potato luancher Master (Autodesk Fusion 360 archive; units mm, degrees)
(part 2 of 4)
sketch "handle moch" plane through (0, 0, 0) normal (1, 0, 0) x axis (0, 1, 0)
  line L1 (69.594, 159.512) -> (83.818, 159.512)
  line L2 (69.594, 145.288) -> (69.594, 159.512)
  line L3 (83.818, 145.288) -> (69.594, 145.288)
  line L4 (83.818, 159.512) -> (83.818, 145.288)
  line L5 (120.5924, 62.217) -> (106.3261, 115.4598)
  line L6 (81.1484, 62.217) -> (120.5924, 62.217)
  line L7 (67.4557, 113.3189) -> (81.1484, 62.217)
  line L8 (457.7082, 152.4) -> (76.706, 152.4)
  line L9 (432.306, 167.4813) -> (305.306, 167.4812)
  line L10 (432.306, 137.3187) -> (432.306, 167.4813)
  line L11 (305.306, 137.3187) -> (432.306, 137.3187)
  line L12 (305.306, 167.4812) -> (305.306, 137.3187)
  line L13 (432.306, 137.3187) -> (305.306, 167.4812)
  line L14 (305.306, 137.3187) -> (432.306, 167.4813)
  line L15 (476.756, 88.9) -> (476.756, -88.9)
  line L16 (44.956, 88.9) -> (44.956, -88.9)
  line L17 (476.756, 88.9) -> (44.956, 88.9)
  line L18 (458.1373, 88.9) -> (432.306, 167.4813)
  line L19 (420.2222, 88.9) -> (404.3059, 137.3187)
  arc A1 centre (76.706, 152.4) radius 25.4 clockwise from (55.9925, 137.6992) to (102.0952, 151.6607)
  arc A2 centre (227.7719, 148.0011) radius 125.73 clockwise from (106.3261, 115.4598) to (102.0952, 151.6607)
  arc A3 centre (-6.1479, 93.5969) radius 76.2 clockwise from (55.9925, 137.6992) to (67.4557, 113.3189)
  circle C1 centre (76.706, 152.4) radius 15.0813
  circle C2 centre (76.706, 152.4) radius 15.0813
  point P15 (76.706, 152.4)
  point P16 (76.706, 152.4)
  point P22 (368.806, 152.4)
  point P26 (44.956, 88.9)
  point P27 (44.956, 88.9)
  point P24 (476.756, 88.9)
  point P28 (476.756, 88.9)
  point P29 (458.1373, 88.9)
  point P30 (404.3059, 137.3187)
  point P31 (420.2222, 88.9)
  point P18 (305.306, 167.4812)
  point P21 (305.306, 137.3187)
  point P19 (432.306, 167.4813)
  coincident P15 P16
  perpendicular L4 L8
  horizontal L9
  perpendicular L9 L10
  parallel L9 L11
  parallel L10 L12
  coincident L13 P22
  coincident L14 P22
  coincident L8 P22
  coincident P26 P27
  coincident P24 P28
  coincident L17 P29
  coincident L11 P30
  coincident L17 P31
  parallel L18 L19
  dimension "d214" distance P18 P21 = 30.1625 (= "d215")
  dimension "d215" diameter C2 = 30.1625
  dimension "d216" distance P18 P19 = 127
  dimension "d217" distance P15 L12 = 228.6
extrude "Extrude1" new body sketch "handle moch" profile of L9 L10 L11 L12 L17 L18 L19 distance 31.75
sketch "Sketch1" plane through (0, 0, 0) normal (0, 1, 0) x axis (-1, 0, 0)
  line L1 (7.9375, -2.4765) -> (-7.9375, -2.4765)
  line L2 (7.9375, 2.4765) -> (7.9375, -2.4765)
  line L3 (-7.9375, 2.4765) -> (7.9375, 2.4765)
  line L4 (-7.9375, -2.4765) -> (-7.9375, 2.4765)
  line L5 (7.9375, 2.4765) -> (-7.9375, -2.4765)
  line L6 (-7.9375, 2.4765) -> (7.9375, -2.4765)
  line L7 (-8.0375, 2.4765) -> (-7.9375, 2.4765)
  line L8 (-8.0375, -2.4765) -> (-8.0375, 2.4765)
  line L9 (-7.9375, -2.4765) -> (-8.0375, -2.4765)
  line L10 (-7.9375, 2.4765) -> (-7.9375, -2.4765)
  line L11 (-9.7875, 2.4765) -> (-8.0375, 2.4765)
  line L12 (-9.7875, -2.5765) -> (-9.7875, 2.4765)
  line L13 (-8.0375, -2.5765) -> (-9.7875, -2.5765)
  line L14 (-8.0375, 2.4765) -> (-8.0375, -2.5765)
  line L15 (-22.5, 0) -> (-1.75, 0)
  line L16 (-9.7855, 2.4765) -> (-7.9375, 2.4765)
  line L17 (-9.7855, 4.81) -> (-9.7855, 2.4765)
  line L18 (-7.9375, 4.81) -> (-9.7855, 4.81)
  line L19 (-7.9375, 2.4765) -> (-7.9375, 4.81)
  line L20 (-15.4644, 4.81) -> (-9.7855, 4.81)
  line L21 (-15.4644, 3.7178) -> (-15.4644, 4.81)
  line L22 (-11.0939, 1.9413) -> (-15.4644, 3.7178)
  line L23 (-15.4644, -4.81) -> (-9.7855, -4.81)
  line L24 (-7.9375, -4.81) -> (-9.7855, -4.81)
  line L25 (-7.9375, -2.4765) -> (-7.9375, -4.81)
  line L26 (-11.0939, -1.9413) -> (-15.4644, -3.7178)
  line L27 (-15.4644, -3.7178) -> (-15.4644, -4.81)
  line L28 (-8.0375, -4.81) -> (-8.0375, -2.5765)
  line L29 (-8.0375, 4.81) -> (-8.0375, 2.4765)
  line L30 (-8.0375, -4.81) -> (-6.7375, -4.81)
  line L31 (-8.0375, -2.5765) -> (-8.0375, -4.81)
  line L32 (-6.7375, -2.5765) -> (-8.0375, -2.5765)
  line L33 (-6.7375, -4.81) -> (-6.7375, -2.5765)
  circle C1 centre (-11.883, 0) radius 2.0955
  point P6 (0, 0)
  point P1 (0, 0)
  point P13 (-11.883, 0)
  point P5 (-7.9375, 2.4765)
  point P24 (-7.9375, -2.4765)
  point P17 (-9.7855, 4.81)
  point P21 (-9.7855, -4.81)
  point P18 (-7.9375, 4.81)
  point P23 (-7.9375, -4.81)
  point P19 (-15.4644, 4.81)
  point P22 (-15.4644, -4.81)
  point P20 (-15.4644, 3.7178)
  point P25 (-15.4644, -3.7178)
  point P26 (-8.0375, -4.81)
  point P27 (-8.0375, 4.81)
  point P28 (-11.0939, 1.9413)
  point P29 (-11.0939, -1.9413)
  point P4 (7.9375, 2.4765)
  point P3 (7.9375, -2.4765)
  point P7 (-8.0375, 2.4765)
  point P10 (-9.7875, 2.4765)
  horizontal L1
  perpendicular L1 L2
  parallel L1 L3
  parallel L2 L4
  coincident L5 P6
  coincident L6 P6
  coincident P1 P6
  horizontal L7
  vertical L8
  horizontal L9
  vertical L10
  horizontal L11
  vertical L12
  horizontal L13
  vertical L14
  coincident P13 L15
  horizontal L16
  vertical L17
  horizontal L18
  vertical L19
  tangent L12 C1
  perpendicular L17 L20
  perpendicular L20 L21
  tangent C1 L22
  symmetric P5 L15 P24
  symmetric L15 P17 P21
  symmetric L15 P18 P23
  symmetric L15 P19 P22
  symmetric L15 P20 P25
  coincident L24 P26
  perpendicular L24 L28
  coincident L18 P27
  perpendicular L18 L29
  coincident C1 P28
  coincident C1 P29
  tangent C1 L26
  horizontal L30
  vertical L31
  horizontal L32
  vertical L33
  coincident P23 L30
  dimension "d220" distance P4 P5 = 15.875
  dimension "d221" distance P3 P4 = 4.953
  dimension "d222" distance P5 P7 = 0.1
  dimension "d223" distance P7 P10 = 1.75
  dimension "d224" diameter C1 = 4.191
  dimension "d225" distance P19 P20 = 1.0922
  dimension "d229" distance L20 L23 = 9.62 (= "0.3 in + 2 mm")
  dimension "d230" distance P13 L27 = 3.5814
  dimension "d231" distance L1 L32 = 0.1 (= "d222")
  dimension "d232" distance L10 L33 = 1.2
revolve "Revolve1" sketch "Sketch1" AlongAngle 360
sketch "spring anchor align" plane through (0, 476.756, 0) normal (0, 1, 0) x axis (-1, 0, 0)
  line L1 (-49.3991, 88.7823) -> (-43.2242, 77.6845)
  line L2 (-52.1735, 87.2385) -> (-49.3991, 88.7823)
  line L3 (-45.9987, 76.1408) -> (-52.1735, 87.2385)
  line L4 (-43.2242, 77.6845) -> (-45.9987, 76.1408)
  line L5 (-52.7144, 94.7406) -> (-49.3991, 88.7823)
  line L6 (-55.4888, 93.1969) -> (-52.7144, 94.7406)
  line L7 (-52.1735, 87.2385) -> (-55.4888, 93.1969)
  line L8 (-49.3991, 88.7823) -> (-52.1735, 87.2385)
  line L9 (0, -29.1936) -> (0, 113.1666)
  line L10 (-2, 90.4654) -> (-2, 108.4001)
  line L11 (0, 0) -> (-50.9577, 95.6969)
  circle C1 centre (0, 0) radius 108.4186
  circle C2 centre (0, 0) radius 88.9
  circle C3 centre (0, 0) radius 88.9
  circle C4 centre (0, 0) radius 90.4875
  point P1 (0, 0)
  point P12 (0, 0)
  point P7 (-52.7144, 94.7406)
  point P14 (-2, 108.4001)
  point P16 (-50.9577, 95.6969)
  point P17 (0, 0)
  point P15 (-2, 90.4654)
  coincident P1 L9
  vertical L9
  coincident P1 P12
  coincident P7 C1
  coincident C1 P14
  parallel L9 L10
  coincident C1 P16
  coincident P1 P17
  coincident P15 C4
  dimension "d233" distance P7 L11 = 2
  dimension "d234" distance L9 L10 = 2 (= "d233")
extrude "Extrude1" new body sketch "spring anchor align" profile of L1 L5 L9 C1 C2 C3 L10 L11 C4 against normal blind 25.4
work_plane "WorkPlane22"
sketch "sp anchor align lable" plane through (26.4789, 0, 102.0485) normal (-0.2512, 0, -0.9679) x axis (0, -1, 0)
  dimension "d540" = 10.0076
emboss "Emboss1" sketch "sp anchor align lable" Depth 2.0066 Horizontal Distance 0 Vertical Distance 0 Rotation Angle 0
extrude "Extrude2" add sketch "spring anchor align" profile of L1 L5 L9 C1 C2 C3 L10 L11 C4 blind -2 from offset -25.4
remove_body "RemoveBody1"
sketch "Sketch2" plane through (0, 76.706, 0) normal (0, -1, 0) x axis (-1, 0, 0)
  line L1 (-66.675, -158.75) -> (66.675, -158.75)
  line L2 (-66.675, -146.05) -> (-66.675, -158.75)
  line L3 (66.675, -146.05) -> (-66.675, -146.05)
  line L4 (66.675, -158.75) -> (66.675, -146.05)
  line L5 (0, -194.1437) -> (0, -158.75)
  line L6 (66.675, -151.6607) -> (63.5, -151.6607)
  line L7 (66.675, -177.8) -> (66.675, -137.6992)
  line L8 (63.5, -137.6992) -> (66.675, -137.6992)
  line L9 (63.5, -177.8) -> (63.5, -137.6992)
  line L10 (61.43, -177.8) -> (63.43, -177.8)
  line L11 (60.43, -167.4813) -> (61.43, -177.8)
  line L12 (0, -167.4813) -> (60.43, -167.4813)
  line L13 (-63.5, -167.4812) -> (-63.5, -137.3187)
  line L14 (-60.43, -167.4813) -> (-61.43, -177.8)
  line L15 (-61.43, -177.8) -> (-63.5, -177.8)
  line L16 (0, -167.4813) -> (-60.43, -167.4813)
  line L17 (-63.5, -158.05) -> (-63.5, -177.8)
  line L18 (63.43, -177.8) -> (63.5, -177.8)
  line L19 (63.43, -158.75) -> (63.43, -177.8)
  line L20 (63.5, -158.75) -> (63.43, -158.75)
  line L21 (63.5, -177.8) -> (63.5, -158.75)
  line L22 (-63.43, -177.8) -> (-63.5, -177.8)
  line L23 (-63.43, -158.75) -> (-63.43, -177.8)
  line L24 (-63.5, -158.75) -> (-63.43, -158.75)
  line L25 (-63.5, -177.8) -> (-63.5, -158.75)
  line L26 (-63.5, -177.8) -> (-63.5, -127)
  line L27 (63.5, -146.05) -> (63.43, -158.75)
  line L28 (42.3915, -152.4) -> (63.465, -152.4)
  point P6 (0, -158.75)
  point P16 (0, -167.4813)
  point P18 (-63.5, -167.4812)
  point P14 (61.43, -177.8)
  point P19 (-61.43, -177.8)
  point P15 (60.43, -167.4813)
  point P20 (-60.43, -167.4813)
  point P22 (0, -167.4813)
  point P23 (-63.5, -158.05)
  point P27 (63.43, -158.75)
  point P13 (63.5, -177.8)
  point P25 (63.5, -177.8)
  point P24 (63.43, -177.8)
  point P26 (63.43, -177.8)
  point P30 (-63.43, -158.75)
  point P34 (63.5, -146.05)
  point P35 (63.465, -152.4)
  point P36 (63.465, -152.4)
  midpoint L1 P6
  perpendicular L1 L5
  perpendicular L9 L10
  coincident L5 P16
  perpendicular L5 L12
  coincident L12 P18
  symmetric L5 P14 P19
  symmetric L5 P15 P20
  symmetric L5 P16 P22
  coincident L13 P23
  perpendicular L1 L17
  horizontal L18
  vertical L19
  horizontal L20
  vertical L21
  coincident L1 P27
  coincident P13 P25
  coincident P24 P26
  horizontal L15
  horizontal L22
  vertical L23
  horizontal L24
  vertical L25
  coincident L1 P30
  coincident L9 P34
  coincident L3 P34
  midpoint L27 P35
  coincident P35 P36
  perpendicular L9 L28
  dimension "d240" distance P25 P26 = 0.07
  dimension "d241" distance P14 P24 = 2
  dimension "d242" distance P15 P24 = 3 (= "d241 * 1.5")
  dimension "d243" distance L23 L26 = 0.07
revolve "Revolve1" sketch "Sketch2" AlongAngle 360
sketch "Sketch22" plane through (-63.43, 0, 0) normal (-1, 0, 0) x axis (0, -1, 0)
  line L1 (-83.056, 158.75) -> (-70.356, 158.75)
  line L2 (-83.056, 146.05) -> (-83.056, 158.75)
  line L3 (-70.356, 146.05) -> (-83.056, 146.05)
  line L4 (-70.356, 158.75) -> (-70.356, 146.05)
  line L5 (-70.156, 145.85) -> (-83.256, 145.85)
  line L6 (-70.156, 158.95) -> (-70.156, 145.85)
  line L7 (-83.256, 158.95) -> (-70.156, 158.95)
  line L8 (-83.256, 145.85) -> (-83.256, 158.95)
  circle C1 centre (-76.706, 152.4) radius 6.35
  circle C2 centre (-76.706, 152.4) radius 25.4
  point P3 (-70.356, 158.75)
  point P6 (-70.356, 146.05)
  dimension "d300" distance P3 P6 = 12.7
  dimension "d301" = 0.2
extrude "Extrude1" cut sketch "Sketch22" profile of C1 L1 L2 L3 L4 L8 L7 L6 L5 against normal blind 126.93
work_plane "WorkPlane1" AlongDistance 17.78
sketch "Sketch3" plane through (0, 52.576, 0) normal (0, -1, 0) x axis (-1, 0, 0)
  line L1 (60.43, -167.4813) -> (60.43, -137.3187)
  line L2 (-60.43, -167.4813) -> (-60.43, -137.3187)
  line L3 (60.43, -167.4813) -> (-60.43, -167.4813)
  line L4 (-60.43, -137.3187) -> (60.43, -137.3187)
  line L5 (-60.43, -152.4) -> (60.43, -152.4)
  line L6 (-27.6126, -276.5613) -> (-13.2272, -282.3759)
  line L7 (-41.998, -282.3759) -> (-27.6126, -276.5613)
  line L8 (-56.3834, -276.5613) -> (-41.998, -282.3759)
  line L9 (-70.7688, -282.3759) -> (-56.3834, -276.5613)
  line L10 (-85.1541, -276.5613) -> (-70.7688, -282.3759)
  line L11 (-99.5395, -282.3759) -> (-85.1541, -276.5613)
  line L12 (-113.9249, -276.5613) -> (-99.5395, -282.3759)
  line L13 (-128.3103, -282.3759) -> (-113.9249, -276.5613)
  line L14 (-142.6957, -276.5613) -> (-128.3103, -282.3759)
  line L15 (-157.0811, -282.3759) -> (-142.6957, -276.5613)
  line L16 (1.1582, -276.5613) -> (-13.2272, -282.3759)
  line L17 (-157.0811, -276.5613) -> (1.1582, -276.5613)
  line L18 (-157.0811, -282.3759) -> (-157.0811, -276.5613)
  line L19 (1.1582, -282.3759) -> (-157.0811, -282.3759)
  line L20 (1.1582, -276.5613) -> (1.1582, -282.3759)
  line L21 (1.9077, -278.4156) -> (-13.2272, -284.533)
  line L22 (-27.6126, -278.7185) -> (-13.2272, -284.533)
  line L23 (-41.998, -284.533) -> (-27.6126, -278.7185)
  line L24 (-56.3834, -278.7185) -> (-41.998, -284.533)
  line L25 (-70.7688, -284.533) -> (-56.3834, -278.7185)
  line L26 (-85.1541, -278.7185) -> (-70.7688, -284.533)
  line L27 (-99.5395, -284.533) -> (-85.1541, -278.7185)
  line L28 (-113.9249, -278.7185) -> (-99.5395, -284.533)
  line L29 (-128.3103, -284.533) -> (-113.9249, -278.7185)
  line L30 (-142.6957, -278.7185) -> (-128.3103, -284.533)
  line L31 (-156.3316, -284.2301) -> (-142.6957, -278.7185)
  curve K1 (56.6004, -155.7426) -> (50.2504, -151.5646)
  curve K2 (43.9004, -147.3866) -> (50.2504, -151.5646)
  line L32 (37.5504, -151.5646) -> (62.9504, -151.5646)
  line L33 (56.6004, -147.3866) -> (56.6004, -155.7426)
  line L34 (43.9004, -155.7426) -> (43.9004, -147.3866)
  line L35 (37.5504, -151.5646) -> (50.2504, -151.5646)
  line L36 (62.9504, -151.5646) -> (50.2504, -151.5646)
  curve K3 (31.2004, -155.7426) -> (24.8504, -151.5646)
  curve K4 (18.5004, -147.3866) -> (24.8504, -151.5646)
  curve K5 (5.8004, -155.7426) -> (-0.5496, -151.5646)
  curve K6 (-6.8996, -147.3866) -> (-0.5496, -151.5646)
  curve K7 (-19.5996, -155.7426) -> (-25.9496, -151.5646)
  curve K8 (-32.2996, -147.3866) -> (-25.9496, -151.5646)
  curve K9 (-44.9996, -155.7426) -> (-51.3496, -151.5646)
  curve K10 (-57.6996, -147.3866) -> (-51.3496, -151.5646)
  curve K11 (49.1511, -153.2354) -> (64.0496, -153.2354)
  curve K12 (49.1511, -153.2354) -> (38.6496, -153.2354)
  curve K13 (23.7511, -153.2354) -> (38.6496, -153.2354)
  curve K14 (23.7511, -153.2354) -> (13.2496, -153.2354)
  curve K15 (-1.6489, -153.2354) -> (13.2496, -153.2354)
  curve K16 (-1.6489, -153.2354) -> (-12.1504, -153.2354)
  curve K17 (-27.0489, -153.2354) -> (-12.1504, -153.2354)
  curve K18 (-27.0489, -153.2354) -> (-37.5504, -153.2354)
  curve K19 (-52.4489, -153.2354) -> (-37.5504, -153.2354)
  curve K20 (-52.4489, -153.2354) -> (-62.9504, -153.2354)
  line L37 (-62.9504, -131.0687) -> (-62.9504, -153.2354)
  line L38 (62.9504, -173.7313) -> (62.9504, -151.5646)
  line L39 (-62.9504, -131.0687) -> (62.9504, -173.7313)
  point P5 (-60.43, -167.4813)
  point P6 (-60.43, -167.4813)
  point P3 (60.43, -167.4813)
  point P7 (60.43, -167.4813)
  point P2 (60.43, -137.3187)
  point P8 (60.43, -137.3187)
  point P4 (-60.43, -137.3187)
  point P9 (-60.43, -137.3187)
  point P10 (60.43, -152.4)
  point P11 (-60.43, -152.4)
  point P12 (-13.2272, -282.3759)
  point P14 (-41.998, -282.3759)
  point P18 (-99.5395, -282.3759)
  point P20 (-128.3103, -282.3759)
  point P21 (-142.6957, -276.5613)
  point P15 (-56.3834, -276.5613)
  point P39 (50.2504, -151.5646)
  point P41 (50.2504, -151.5646)
  point P43 (37.5504, -151.5646)
  point P45 (37.5504, -151.5646)
  point P38 (62.9504, -151.5646)
  point P44 (62.9504, -151.5646)
  point P85 (0, -152.4)
  point P86 (0, -152.4)
  coincident P5 P6
  coincident P3 P7
  coincident P2 P8
  coincident P4 P9
  midpoint L1 P10
  midpoint L2 P11
  parallel L6 L8
  parallel L7 L9
  parallel L11 L13
  parallel L13 L15
  equal L14 L15
  equal L13 L14
  equal L11 L12
  equal L12 L13
  equal L10 L11
  equal L8 L9
  equal L9 L10
  equal L7 L8
  equal L6 L7
  equal L6 L16
  horizontal L17
  vertical L18
  horizontal L19
  vertical L20
  coincident P12 L19
  coincident P14 L19
  coincident P18 L19
  coincident P20 L19
  coincident P21 L17
  coincident P15 L17
  coincident P39 P41
  horizontal L32
  coincident P43 P45
  coincident P38 P44
  coincident P39 L32
  vertical L33
  vertical L34
  midpoint L34 L35
  midpoint L33 L36
  equal L33 L34
  equal L35 L36
  vertical L37
  perpendicular L36 L38
  equal L37 L38
  coincident L39 P85
  midpoint L39 P85
  midpoint L5 P86
  coincident P85 P86
  dimension "d245" = -2
  dimension "d247" distance P38 P43 = 25.4
  dimension "d252" = -2
  dimension "d250" R-Pattern1-uDistance = -25.4
  dimension "d251" R-Pattern1-vDistance = 0
emboss "Emboss1" sketch "Sketch3" Depth 1.3 Horizontal Distance 0 Vertical Distance 0 Rotation Angle 0
circular_pattern "C-Pattern1" countU 17 TotalAngle 360
sketch "Sketch2" plane through (0, 0, 0) normal (0, 1, 0) x axis (1, 0, 0)
  line L1 (6.7375, 2.5765) -> (-6.7375, 2.5765)
  line L2 (6.7375, 4.81) -> (-6.7375, 4.81)
  line L3 (15.4644, -4.81) -> (-15.4644, -4.81)
  line L4 (0, -45.2489) -> (0, 7.043)
  line L5 (-3.175, 2.5765) -> (3.175, 2.5765)
  line L6 (-3.175, -16.4735) -> (-3.175, 2.5765)
  line L7 (3.175, -16.4735) -> (-3.175, -16.4735)
  line L8 (3.175, 2.5765) -> (3.175, -16.4735)
  line L9 (-3.175, -16.4735) -> (3.175, 2.5765)
  line L10 (3.175, -16.4735) -> (-3.175, 2.5765)
  line L11 (-4.7117, 8.9265) -> (4.7117, 8.9265)
  line L12 (-4.7117, 2.5765) -> (-4.7117, 8.9265)
  line L13 (4.7117, 2.5765) -> (-4.7117, 2.5765)
  line L14 (4.7117, 8.9265) -> (4.7117, 2.5765)
  line L15 (-4.7117, 2.5765) -> (4.7117, 8.9265)
  line L16 (4.7117, 2.5765) -> (-4.7117, 8.9265)
  line L17 (3.175, -16.4735) -> (-3.175, -16.4735)
  line L18 (3.175, -9.6663) -> (3.175, -16.4735)
  line L19 (-3.175, -9.6663) -> (3.175, -9.6663)
  line L20 (-3.175, -16.4735) -> (-3.175, -9.6663)
  line L21 (13.3232, -9.6663) -> (-4.8965, -9.6663)
  line L22 (13.3232, -6.4913) -> (13.3232, -9.6663)
  line L23 (-4.8965, -6.4913) -> (13.3232, -6.4913)
  line L24 (-4.8965, -9.6663) -> (-4.8965, -6.4913)
  line L25 (15.4644, 4.81) -> (15.4644, -4.81)
  line L26 (21.2101, 0) -> (15.4644, 0)
  line L27 (6.7375, -2.5765) -> (-6.7375, -2.5765)
  line L28 (3.325, -6.4913) -> (3.325, -2.5765)
  line L29 (4.849, -2.5765) -> (4.849, -6.4913)
  point P14 (0, -6.9485)
  point P1 (0, 0)
  point P19 (0, 5.7515)
  point P10 (3.175, 2.5765)
  point P21 (3.175, -9.6663)
  point P18 (4.7117, 2.5765)
  point P7 (15.4644, -4.81)
  point P27 (15.4644, -4.81)
  point P28 (15.4644, 4.81)
  point P29 (15.4644, 0)
  point P2 (-6.7375, 2.5765)
  point P31 (-6.7375, -2.5765)
  point P3 (6.7375, 2.5765)
  point P32 (6.7375, -2.5765)
  point P33 (3.325, -2.5765)
  point P34 (3.325, -6.4913)
  point P35 (4.849, -6.4913)
  point P36 (4.849, -2.5765)
  point P11 (-3.175, 2.5765)
  point P12 (-3.175, -16.4735)
  point P13 (3.175, -16.4735)
  point P17 (-4.7117, 2.5765)
  point P16 (-4.7117, 8.9265)
  point P24 (13.3232, -9.6663)
  point P25 (13.3232, -6.4913)
  perpendicular L3 L4
  horizontal L5
  perpendicular L5 L6
  parallel L5 L7
  parallel L6 L8
  coincident L9 P14
  coincident L10 P14
  coincident L4 P14
  coincident P1 L4
  horizontal L11
  perpendicular L11 L12
  parallel L11 L13
  parallel L12 L14
  coincident L15 P19
  coincident L16 P19
  coincident L4 P19
  coincident P10 L13
  horizontal L17
  vertical L18
  horizontal L19
  vertical L20
  coincident L8 P21
  coincident L1 P18
  horizontal L21
  vertical L22
  horizontal L23
  vertical L24
  coincident P21 L21
  coincident P7 P27
  vertical L25
  coincident L2 P28
  midpoint L25 P29
  perpendicular L25 L26
  symmetric P2 L26 P31
  symmetric P3 L26 P32
  coincident L27 P33
  coincident L23 P34
  perpendicular L23 L28
  coincident L23 P35
  coincident L27 P36
  perpendicular L27 L29
  dimension "d273" distance P11 P12 = 19.05
  dimension "d274" distance P12 P13 = 6.35
  dimension "d275" distance P17 P18 = 9.4234
  dimension "d276" distance P16 P17 = 6.35
  dimension "d277" distance L7 L19 = 6.8072 (= "0.308 in - 0.04 in")
  dimension "d278" distance P24 P25 = 3.175
  dimension "d279" distance L8 L28 = 0.15
  dimension "d280" distance L28 L29 = 1.524
work_plane "WorkPlane23" AlongDistance 127
sketch "Fwd ahndle align" plane through (0, 127, 0) normal (0, 1, 0) x axis (1, 0, 0)
  line L1 (0, -131.9689) -> (0, 0)
  line L2 (-3, -131.9689) -> (-3, 0)
  line L3 (-63.5, -115.4598) -> (-66.675, -115.4598)
  line L4 (-63.5, -62.217) -> (-63.5, -115.4598)
  line L5 (-66.675, -62.217) -> (-63.5, -62.217)
  line L6 (-66.675, -115.4598) -> (-66.675, -62.217)
  line L7 (-60.5, -62.217) -> (-60.5, -115.4598)
  line L8 (42.5299, -79.8698) -> (50.9577, -95.6969)
  line L9 (2, -108.4001) -> (2, -90.4654)
  line L10 (-60.5, -67.2885) -> (-60.5, -118.0885)
  line L11 (-63.5, -118.0885) -> (-60.5, -118.0885)
  line L12 (-63.5, -115.4598) -> (-63.5, -118.0885)
  arc A1 centre (0, 0) radius 90.4875 clockwise from (42.5299, -79.8698) to (2, -90.4654)
  arc A2 centre (0, 0) radius 108.4186 clockwise from (50.9577, -95.6969) to (2, -108.4001)
  arc A3 centre (0, 0) radius 108.4186 clockwise from (0, -108.4186) to (-63.5, -87.8768)
  circle C1 centre (0, 0) radius 90.4875
  circle C2 centre (0, 0) radius 88.9
  circle C3 centre (0, 0) radius 88.9
  arc A4 centre (0, 0) radius 108.4186 clockwise from (2, -108.4001) to (-11.8587, -107.7681)
  point P1 (0, 0)
  point P2 (0, 0)
  point P19 (0, -108.4186)
  point P17 (0, 0)
  point P18 (-63.5, -87.8768)
  point P20 (-60.5, -118.0885)
  point P21 (-60.5, -67.2885)
  point P7 (-63.5, -115.4598)
  point P24 (-63.5, -115.4598)
  point P16 (2, -108.4001)
  point P28 (2, -108.4001)
  point P26 (0, 0)
  point P27 (-11.8587, -107.7681)
  coincident P1 P2
  vertical L1
  coincident L1 P19
  coincident P1 P17
  coincident L4 P18
  coincident L7 P20
  coincident L7 P21
  coincident P21 C1
  perpendicular L4 L11
  coincident P7 P24
  perpendicular L3 L12
  coincident P16 P28
  coincident P1 P26
  coincident A3 P27
  dimension "d549" = 3
  dimension "d550" = 3
  dimension "d551" distance P20 P21 = 50.8
extrude "Extrude1" new body sketch "Fwd ahndle align" profile of L1 L2 L4 L7 A3 L10 C1 L11 L12 C2 C3 against normal blind 63.5
extrude "Extrude2" add sketch "Fwd ahndle align" profile of L1 L2 L4 L7 A3 L10 C1 L11 L12 C2 C3 blind -3 from offset -63.5
work_plane "WorkPlane24"
sketch "Sketch45" plane through (-31.75, 0, 99.1728) normal (-0.3049, 0, 0.9524) x axis (0, -1, 0)
  dimension "d562" = 10.0076
emboss "Emboss1" sketch "Sketch45" Depth 2.0066 Horizontal Distance 0 Vertical Distance 0 Rotation Angle 0
remove_instance "RemoveInstance3"
place_component sketch "Sketch2"
revolve "Revolve1" sketch "Sketch2" AlongAngle 360
sketch "Sketch3" plane through (0, 0, 6.4913) normal (0, 0, 1) x axis (-1, 0, 0)
  line L1 (0, 67.1034) -> (0, -37.4981)
  line L2 (12.7, 139.7) -> (-12.7, 139.7)
  line L3 (12.7, 0) -> (12.7, 139.7)
  line L4 (-12.7, 0) -> (12.7, 0)
  line L5 (-12.7, 139.7) -> (-12.7, 0)
  line L6 (12.7, 0) -> (-12.7, 139.7)
  line L7 (-12.7, 0) -> (12.7, 139.7)
  circle C1 centre (0, 0) radius 4.849
  circle C2 centre (0, 0) radius 3.325
  circle C3 centre (0, 0) radius 3.175
  circle C4 centre (0, 0) radius 12.7
  point P2 (0, 0)
  point P10 (0, 69.85)
  point P9 (-12.7, 0)
  point P7 (12.7, 139.7)
  point P8 (12.7, 0)
  concentric C1 C3
  vertical L1
  coincident P2 L1
  horizontal L2
  perpendicular L2 L3
  parallel L2 L4
  parallel L3 L5
  coincident L6 P10
  coincident L7 P10
  coincident L1 P10
  concentric C3 C4
  coincident P9 C4
  tangent L5 C4
  dimension "d282" diameter C3 = 6.35
  dimension "d283" distance P7 P8 = 139.7
  dimension "d284" diameter C4 = 25.4
place_component sketch "Sketch3"
face "Face1" sketch "Sketch3"
remove_instance "RemoveInstance2"
component_from_bodies "Body->Comp"
position "Position3"
position "Position7"
as_built_joint "As-built3"
work_plane "WorkPlane11"
sketch "aft handle main" plane through (0, 0, 0) normal (1, 0, 0) x axis (0, 1, 0)
  line L1 (415.956, 171.45) -> (250.2367, 171.45)
  line L2 (415.956, 133.35) -> (415.956, 171.45)
  line L3 (250.2367, 133.35) -> (415.956, 133.35)
  line L4 (250.2367, 171.45) -> (250.2367, 133.35)
  line L5 (238.88, 152.4) -> (76.706, 152.4)
  line L6 (216.756, 126.0311) -> (155.756, 126.0311)
  line L7 (216.756, 39.9354) -> (216.756, 126.0311)
  line L8 (155.756, 39.9354) -> (216.756, 39.9354)
  line L9 (155.756, 126.0311) -> (155.756, 39.9354)
  line L10 (527.556, 90.4875) -> (527.556, -90.4875)
  line L11 (476.756, 90.4875) -> (476.756, -90.4875)
  line L12 (476.756, 90.4875) -> (476.756, -90.4875)
  line L13 (466.756, 98.8205) -> (415.956, 98.8205)
  line L14 (466.756, 88.9) -> (466.756, 98.8205)
  line L15 (415.956, 88.9) -> (466.756, 88.9)
  line L16 (415.956, 98.8205) -> (415.956, 88.9)
  line L17 (476.756, 88.9) -> (476.756, -88.9)
  line L18 (44.956, 88.9) -> (44.956, -88.9)
  line L19 (415.956, 133.35) -> (415.956, 98.8205)
  line L20 (466.756, 171.45) -> (466.756, 98.8205)
  line L21 (254.2367, 137.35) -> (411.956, 137.35)
  line L22 (254.2367, 167.45) -> (254.2367, 137.35)
  line L23 (411.956, 167.45) -> (254.2367, 167.45)
  line L24 (411.956, 137.35) -> (411.956, 167.45)
  line L25 (272.2367, 133.35) -> (250.2367, 133.35)
  line L26 (272.2367, 118.35) -> (272.2367, 133.35)
  line L27 (250.2367, 118.35) -> (272.2367, 118.35)
  line L28 (250.2367, 133.35) -> (250.2367, 118.35)
  line L29 (272.2367, 118.35) -> (276.256, 133.35)
  line L30 (276.256, 206.4752) -> (415.956, 206.4752)
  line L31 (276.256, 71.2796) -> (276.256, 100.7562)
  circle C1 centre (76.706, 152.4) radius 25.4
  point P6 (76.706, 152.4)
  point P7 (76.706, 152.4)
  point P24 (476.756, 88.9)
  point P27 (250.2367, 152.4)
  point P28 (415.956, 133.35)
  point P29 (466.756, 171.45)
  point P37 (276.256, 133.35)
  point P39 (276.256, 206.4752)
  point P38 (415.956, 206.4752)
  point P4 (415.956, 133.35)
  point P2 (250.2367, 171.45)
  point P5 (250.2367, 133.35)
  point P9 (155.756, 126.0311)
  point P10 (216.756, 126.0311)
  point P19 (415.956, 98.8205)
  point P20 (466.756, 98.8205)
  point P21 (466.756, 88.9)
  point P34 (272.2367, 133.35)
  point P36 (250.2367, 118.35)
  horizontal L1
  vertical L2
  horizontal L3
  vertical L4
  coincident P6 P7
  horizontal L5
  horizontal L6
  vertical L7
  horizontal L8
  vertical L9
  horizontal L13
  vertical L14
  horizontal L15
  vertical L16
  coincident L15 P24
  midpoint L4 P27
  coincident L5 P27
  coincident L3 P28
  perpendicular L3 L19
  coincident L1 P29
  vertical L20
  horizontal L25
  vertical L26
  horizontal L27
  vertical L28
  coincident L3 P37
  horizontal L30
  vertical L31
  coincident P37 L31
  coincident P39 L31
  coincident L2 P38
  coincident P4 L19
  dimension "d309" distance P2 P5 = 38.1
  dimension "d310" distance P9 P10 = 61
  dimension "d311" distance L7 L12 = 260
  dimension "d312" distance P19 P20 = 50.8 (= "2")
  dimension "d313" distance L12 P21 = 10
  dimension "d329" = 4
  dimension "d347" distance P5 P34 = 22
  dimension "d348" distance P5 P36 = 15
  dimension "d349" angle L26 L29 = 15
  dimension "d361" distance P38 P39 = 139.7
work_plane "WorkPlane14" AlongDistance 250.2408
sketch "Aft handle 1" plane through (0, 250.2367, 0) normal (0, 1, 0) x axis (1, 0, 0)
  line L1 (0, -171.45) -> (0, -133.35)
  line L2 (0, -133.35) -> (0, -118.35)
  line L3 (16, -133.35) -> (-16, -133.35)
  line L4 (16, -171.45) -> (16, -133.35)
  line L5 (-16, -171.45) -> (16, -171.45)
  line L6 (-16, -133.35) -> (-16, -171.45)
  line L7 (16, -171.45) -> (-16, -133.35)
  line L8 (-16, -171.45) -> (16, -133.35)
  line L9 (-44.925, -118.35) -> (33.065, -118.35)
  arc A1 centre (73.7256, -152.4) radius 91.7256 clockwise from (-16, -171.45) to (-16, -133.35)
  arc A2 centre (73.7256, -152.4) radius 91.7256 clockwise from (-16, -171.45) to (-11.4459, -118.35)
  arc A3 centre (-73.7256, -152.4) radius 91.7256 clockwise from (11.4459, -118.35) to (16, -171.45)
  arc A4 centre (0, -150.1021) radius 33.7521 clockwise from (-11.4459, -118.35) to (11.4459, -118.35)
  arc A5 centre (0, -108.45) radius 65 clockwise from (16, -171.45) to (-16, -171.45)
  point P10 (0, -152.4)
  point P4 (0, -152.4)
  point P3 (0, -171.45)
  point P12 (-18, -152.4)
  point P5 (0, -118.35)
  point P16 (-11.4459, -118.35)
  point P11 (73.7256, -152.4)
  point P15 (73.7256, -152.4)
  point P9 (-16, -171.45)
  point P19 (16, -171.45)
  point P18 (11.4459, -118.35)
  point P21 (0, -116.35)
  point P24 (0, -173.45)
  point P8 (16, -171.45)
  point P22 (0, -118.35)
  horizontal L3
  perpendicular L3 L4
  parallel L3 L5
  parallel L4 L6
  coincident L7 P10
  coincident L8 P10
  coincident P4 P10
  coincident P3 L5
  midpoint A1 P12
  horizontal L9
  coincident P5 L9
  coincident L9 P16
  coincident P11 P15
  symmetric L1 P9 P19
  symmetric L1 P16 P18
  symmetric L1 A2 A3
  midpoint A4 P21
  midpoint A5 P24
  dimension "d363" distance P8 P9 = 32
  dimension "d364" distance L6 P12 = 2
  dimension "d365" distance P21 P22 = 2
  dimension "d366" distance L5 P24 = 2
work_plane "WorkPlane16" AlongDistance 21.9964
sketch "aft handle 2" plane through (0, 272.2367, 0) normal (0, 1, 0) x axis (1, 0, 0)
  arc A1 centre (0, -108.45) radius 65 clockwise from (16, -171.45) to (-16, -171.45)
  arc A2 centre (-73.7256, -152.4) radius 91.7256 clockwise from (11.4459, -118.35) to (16, -171.45)
  arc A3 centre (0, -150.1021) radius 33.7521 clockwise from (-11.4459, -118.35) to (11.4459, -118.35)
  arc A4 centre (73.7256, -152.4) radius 91.7256 clockwise from (-16, -171.45) to (-11.4459, -118.35)
work_plane "WorkPlane17" AlongDistance 26.0096
sketch "Aft handle 3" plane through (0, 276.256, 0) normal (0, 1, 0) x axis (1, 0, 0)
  line L1 (16, -133.35) -> (-16, -133.35)
  arc A1 centre (0, -108.45) radius 65 clockwise from (16, -171.45) to (-16, -171.45)
  arc A2 centre (73.7256, -152.4) radius 91.7256 clockwise from (-16, -171.45) to (-11.4459, -118.35)
  arc A3 centre (-73.7256, -152.4) radius 91.7256 clockwise from (11.4459, -118.35) to (16, -171.45)
  arc A4 centre (0, -196.35) radius 65 clockwise from (-16, -133.35) to (16, -133.35)
  point P9 (-16, -133.35)
  point P12 (-16, -133.35)
  point P10 (16, -133.35)
  point P11 (16, -133.35)
  point P14 (0, -131.35)
  coincident P9 P12
  coincident P10 P11
  midpoint A4 P14
  dimension "d372" distance L1 P14 = 2
work_plane "WorkPlane18" AlongDistance 415.9504
sketch "Sketch30" plane through (0, 415.956, 0) normal (0, 1, 0) x axis (1, 0, 0)
  arc A1 centre (-73.7256, -152.4) radius 91.7256 clockwise from (11.4459, -118.35) to (16, -171.45)
  arc A2 centre (0, -108.45) radius 65 clockwise from (16, -171.45) to (-16, -171.45)
  arc A3 centre (73.7256, -152.4) radius 91.7256 clockwise from (-16, -171.45) to (-11.4459, -118.35)
  arc A4 centre (0, -196.35) radius 65 clockwise from (-16, -133.35) to (16, -133.35)
remove_body "RemoveBody3"
loft "Loft1" sketch "Aft handle 1" + "aft handle 2"
loft "Loft2" sketch "Aft handle 3"
loft "Loft3" sketch "Sketch30"
shell "Shell1" sketch "tank profile" innerThickness 4
split "Split1" bodies "left"
sketch "Sketch2" plane through (0, 0, 0) normal (-1, 0, 0) x axis (0, -1, 0)
  line L1 (-250.2367, 173.45) -> (-250.2367, 116.35)
  line L2 (-415.956, 173.45) -> (-250.2367, 173.45)
  line L3 (-415.956, 169.45) -> (-415.956, 173.45)
  line L4 (-254.2367, 169.45) -> (-415.956, 169.45)
  line L5 (-254.2367, 120.35) -> (-254.2367, 169.45)
  line L6 (-269.1674, 120.35) -> (-254.2367, 120.35)
  line L7 (-269.1674, 120.35) -> (-273.1866, 135.35)
  line L8 (-415.956, 135.35) -> (-273.1866, 135.35)
  line L9 (-415.956, 131.35) -> (-415.956, 135.35)
  line L10 (-276.256, 131.35) -> (-415.956, 131.35)
  line L11 (-276.256, 131.35) -> (-272.2367, 116.35)
  line L12 (-250.2367, 116.35) -> (-272.2367, 116.35)
  line L13 (-250.2367, 116.35) -> (-250.2367, 173.45)
  line L14 (-272.2367, 116.35) -> (-250.2367, 116.35)
  line L15 (-276.256, 131.35) -> (-272.2367, 116.35)
  line L16 (-415.956, 131.35) -> (-276.256, 131.35)
  line L17 (-415.956, 135.35) -> (-415.956, 131.35)
  line L18 (-273.1866, 135.35) -> (-415.956, 135.35)
  line L19 (-269.1674, 120.35) -> (-273.1866, 135.35)
  line L20 (-254.2367, 120.35) -> (-269.1674, 120.35)
  line L21 (-254.2367, 169.45) -> (-254.2367, 120.35)
  line L22 (-415.956, 169.45) -> (-254.2367, 169.45)
  line L23 (-415.956, 173.45) -> (-415.956, 169.45)
  line L24 (-250.2367, 173.45) -> (-415.956, 173.45)
  line L25 (-257.1024, 123.2157) -> (-266.9685, 123.2157)
  line L26 (-257.1024, 166.5843) -> (-257.1024, 123.2157)
  line L27 (-418.8216, 166.5843) -> (-257.1024, 166.5843)
  line L28 (-418.8216, 176.3157) -> (-418.8216, 166.5843)
  line L29 (-247.3711, 176.3157) -> (-418.8216, 176.3157)
  line L30 (-247.3711, 113.4843) -> (-247.3711, 176.3157)
  line L31 (-274.4356, 113.4843) -> (-247.3711, 113.4843)
  line L32 (-278.4549, 128.4843) -> (-274.4356, 113.4843)
  line L33 (-418.8216, 128.4843) -> (-278.4549, 128.4843)
  line L34 (-418.8216, 138.2157) -> (-418.8216, 128.4843)
  line L35 (-270.9877, 138.2157) -> (-418.8216, 138.2157)
  line L36 (-266.9685, 123.2157) -> (-270.9877, 138.2157)
  line L37 (-321.7775, 135.35) -> (-321.7775, 138.2157)
  line L38 (-322.8085, 166.5843) -> (-322.8085, 169.45)
  point P38 (-321.7775, 138.2157)
  point P39 (-321.7775, 135.35)
  point P40 (-322.8085, 169.45)
  point P41 (-322.8085, 166.5843)
  coincident L35 P38
  coincident L18 P39
  perpendicular L18 L37
  coincident L4 P40
  coincident L27 P41
  perpendicular L27 L38
  dimension "d375" = -2.8657
extrude "Extrude1" cut sketch "Sketch2" profile of L4 L5 L6 L7 L8 L18 L19 L20 L21 L22 L36 L35 L27 L25 L26 L37 L38 distance 8.25
sketch "Sketch3" plane through (0, 0, 0) normal (-1, 0, 0) x axis (0, -1, 0)
  line L1 (-250.2367, 173.45) -> (-250.2367, 116.35)
  line L2 (-415.956, 173.45) -> (-250.2367, 173.45)
  line L3 (-415.956, 169.45) -> (-415.956, 173.45)
  line L4 (-322.8085, 169.45) -> (-415.956, 169.45)
  line L5 (-254.2367, 169.45) -> (-322.8085, 169.45)
  line L6 (-254.2367, 120.35) -> (-254.2367, 169.45)
  line L7 (-269.1674, 120.35) -> (-254.2367, 120.35)
  line L8 (-269.1674, 120.35) -> (-273.1866, 135.35)
  line L9 (-321.7775, 135.35) -> (-273.1866, 135.35)
  line L10 (-415.956, 135.35) -> (-321.7775, 135.35)
  line L11 (-415.956, 131.35) -> (-415.956, 135.35)
  line L12 (-276.256, 131.35) -> (-415.956, 131.35)
  line L13 (-276.256, 131.35) -> (-272.2367, 116.35)
  line L14 (-250.2367, 116.35) -> (-272.2367, 116.35)
  line L15 (-255.7367, 167.95) -> (-322.8085, 167.95)
  line L16 (-255.7367, 121.85) -> (-255.7367, 167.95)
  line L17 (-268.0164, 121.85) -> (-255.7367, 121.85)
  line L18 (-268.0164, 121.85) -> (-272.0357, 136.85)
  line L19 (-321.7775, 136.85) -> (-272.0357, 136.85)
  line L20 (-278.9967, 135.35) -> (-313.4688, 135.35)
  line L21 (-278.9967, 141.85) -> (-278.9967, 135.35)
  line L22 (-313.4688, 141.85) -> (-278.9967, 141.85)
  line L23 (-313.4688, 135.35) -> (-313.4688, 141.85)
  line L24 (-313.4688, 131.35) -> (-313.4688, 135.35)
  line L25 (-278.9967, 123.4258) -> (-278.9967, 135.35)
  line L26 (-263.8509, 141.85) -> (-278.9967, 141.85)
  line L27 (-260.0435, 127.6406) -> (-263.8509, 141.85)
  line L28 (-319.7775, 141.85) -> (-313.4688, 141.85)
  line L29 (-319.7775, 135.65) -> (-319.7775, 141.85)
  line L30 (-313.4688, 135.65) -> (-319.7775, 135.65)
  line L31 (-313.4688, 141.85) -> (-313.4688, 135.65)
  circle C1 centre (-264.4867, 126.45) radius 1.6
  circle C2 centre (-264.4867, 126.45) radius 4.6
  arc A1 centre (-229.7424, 131.35) radius 83.7264 clockwise from (-311.5111, 113.35) to (-313.4688, 131.35)
  arc A2 centre (-274.4187, 51.1532) radius 72.4175 clockwise from (-311.5111, 113.35) to (-278.9967, 123.4258)
  point P24 (-313.4688, 135.35)
  point P28 (-313.4688, 131.35)
  point P34 (-260.0435, 127.6406)
  point P35 (-312.978, 122.2969)
  point P26 (-278.9967, 141.85)
  point P29 (-278.9967, 123.4258)
  point P30 (-311.5111, 113.35)
  point P21 (-321.7775, 136.85)
  point P37 (-319.7775, 135.65)
  horizontal L20
  vertical L21
  horizontal L22
  vertical L23
  coincident L9 P24
  coincident L12 P28
  perpendicular L12 L24
  perpendicular L12 L25
  tangent L24 A1
  perpendicular L21 L26
  coincident C2 P34
  tangent C2 L27
  parallel L18 L27
  midpoint A1 P35
  horizontal L28
  vertical L29
  horizontal L30
  vertical L31
  tangent L17 C2
  tangent L18 C2
  dimension "d378" = 1.5
  dimension "d379" diameter C1 = 3.2
  dimension "d380" = 3
  dimension "d382" distance L19 P26 = 5
  dimension "d384" distance P29 P35 = 34
  dimension "d385" distance L12 P30 = 18
  dimension "d386" distance P21 L29 = 2
  dimension "d387" distance L9 P37 = 0.3
extrude "Extrude1" new body sketch "Sketch3" profile of L9 L12 L18 L19 C1 C2 L20 L21 L22 L23 L24 L25 A1 A2 L26 L27 L28 L29 L30 L31 distance 10
sketch "Sketch3" plane through (0, 0, 135.65) normal (0, 0, -1) x axis (1, 0, 0)
  line L1 (-5, -313.4688) -> (5, -313.4688)
  line L2 (-5, -319.7775) -> (-5, -313.4688)
  line L3 (5, -319.7775) -> (-5, -319.7775)
  line L4 (5, -313.4688) -> (5, -319.7775)
  line L5 (-5, -311.5111) -> (5, -311.5111)
  line L6 (-5, -313.4688) -> (-5, -311.5111)
  line L7 (5, -313.4688) -> (-5, -313.4688)
  line L8 (5, -311.5111) -> (5, -313.4688)
  line L9 (-5, -278.9967) -> (5, -278.9967)
  line L10 (-5, -278.9967) -> (-5, -311.5111)
  line L11 (5, -311.5111) -> (-5, -311.5111)
  line L12 (5, -311.5111) -> (5, -278.9967)
  line L13 (-6, -277.9967) -> (-6, -312.5111)
  line L14 (-6, -277.9967) -> (6, -277.9967)
  line L15 (6, -312.5111) -> (6, -277.9967)
  line L16 (6, -312.5111) -> (-6, -312.5111)
  line L17 (6, -312.5111) -> (-6, -312.5111)
  line L18 (6, -315.4811) -> (6, -312.5111)
  line L19 (-6, -315.4811) -> (6, -315.4811)
  line L20 (-6, -312.5111) -> (-6, -315.4811)
  point P17 (6, -312.5111)
  point P18 (6, -312.5111)
  point P19 (6, -315.4811)
  horizontal L17
  vertical L18
  horizontal L19
  vertical L20
  coincident P17 L18
  dimension "d390" = 1
  dimension "d391" distance P18 P19 = 2.97 (= "5 mm - 2.03 mm")
extrude "Extrude2" cut sketch "Sketch3" profile of L1 L2 L4 L5 L6 L7 L8 L9 L10 L11 L12 L16 L15 L14 L13 L17 L18 L19 L20 along normal blind 22.3
as_built_joint "As-built2" OffsetX 0 OffsetY 0 OffsetZ 0 AngleZ 0
ground "Ground3"
position "Position10"
sketch "Sketch42" plane through (0, 0, 0) normal (1, 0, 0) x axis (0, 1, 0)
  line L1 (277.9967, 135.35) -> (277.9967, 131.35)
  line L2 (273.1866, 135.35) -> (277.9967, 135.35)
  line L3 (269.1674, 120.35) -> (273.1866, 135.35)
  line L4 (254.2367, 120.35) -> (269.1674, 120.35)
  line L5 (254.2367, 169.45) -> (254.2367, 120.35)
  line L6 (322.8085, 169.45) -> (254.2367, 169.45)
  line L7 (415.956, 169.45) -> (322.8085, 169.45)
  line L8 (415.956, 173.45) -> (415.956, 169.45)
  line L9 (250.2367, 173.45) -> (415.956, 173.45)
  line L10 (250.2367, 116.35) -> (250.2367, 173.45)
  line L11 (272.2367, 116.35) -> (250.2367, 116.35)
  line L12 (276.256, 131.35) -> (272.2367, 116.35)
  line L13 (277.9967, 131.35) -> (276.256, 131.35)
  line L14 (258.6534, 140.7166) -> (311.249, 159.7294)
  line L15 (259.9034, 126.0591) -> (258.6534, 140.7166)
  line L16 (268.0505, 138.7969) -> (269.0701, 126.8409)
  line L17 (274.5969, 141.1634) -> (268.0505, 138.7969)
  line L18 (279.1606, 128.5387) -> (274.5969, 141.1634)
  line L19 (307.4238, 151.754) -> (308.8857, 147.7101)
  line L20 (313.3568, 153.8987) -> (307.4238, 151.754)
  line L21 (311.249, 159.7294) -> (313.3568, 153.8987)
  line L22 (277.5767, 129.9788) -> (275.0271, 137.0319)
  line L23 (279.1606, 128.5387) -> (274.5969, 141.1634)
  line L24 (277.9967, 135.35) -> (315.4811, 135.35)
  line L25 (277.9967, 131.6275) -> (277.9967, 135.35)
  line L26 (315.4811, 131.6275) -> (277.9967, 131.6275)
  line L27 (315.4811, 135.35) -> (315.4811, 131.6275)
  line L28 (275.5917, 135.35) -> (277.9967, 135.35)
  line L29 (277.1263, 131.35) -> (277.9967, 131.35)
  circle C1 centre (264.4867, 126.45) radius 1.6
  arc A1 centre (264.4867, 126.45) radius 4.6 clockwise from (269.0701, 126.8409) to (259.9034, 126.0591)
  arc A2 centre (299.4251, 59.0143) radius 72.4175 clockwise from (279.1606, 128.5387) to (313.1638, 130.1166)
  arc A3 centre (230.146, 119.2465) radius 83.7264 clockwise from (308.8857, 147.7101) to (313.1638, 130.1166)
  point P34 (277.9967, 135.35)
  point P37 (277.9967, 135.35)
  point P38 (275.5917, 135.35)
  point P2 (277.9967, 131.35)
  point P39 (277.9967, 131.35)
  point P40 (277.1263, 131.35)
  parallel L22 L23
  coincident P34 P37
  midpoint L2 P38
  coincident P2 P39
  midpoint L13 P40
  dimension "d531" distance L22 L23 = 1
extrude "Extrude7" cut sketch "Sketch42" profile of L1 L2 L13 L18 L22 L23 L25 L28 L29 distance -6
position "Position11" RotateAboutZ 0
sketch "Sketch31" plane through (-5, 0, 0) normal (-1, 0, 0) x axis (0, -1, 0)
  line L1 (-278.9967, 136.85) -> (-278.9967, 123.4258)
  line L2 (-272.0357, 136.85) -> (-278.9967, 136.85)
  line L3 (-263.8509, 141.85) -> (-260.0435, 127.6406)
  line L4 (-319.7775, 141.85) -> (-263.8509, 141.85)
  line L5 (-319.7775, 135.65) -> (-319.7775, 141.85)
  line L6 (-313.4688, 135.65) -> (-319.7775, 135.65)
  line L7 (-313.4688, 131.35) -> (-313.4688, 135.65)
  line L8 (-279.0207, 162.9256) -> (-272.0357, 136.85)
  line L9 (-322.8085, 169.45) -> (-322.8085, 168.8895)
  line L10 (-254.2367, 168.8895) -> (-322.8085, 168.8895)
  line L11 (-254.2367, 168.1395) -> (-254.2367, 168.8895)
  line L12 (-272.2351, 168.1395) -> (-254.2367, 168.1395)
  curve K1 (-276.2591, 168.1395) -> (-272.2351, 168.1395)
  line L13 (-415.956, 168.1395) -> (-276.2591, 168.1395)
  line L14 (-415.956, 169.45) -> (-415.956, 168.1395)
  line L15 (-322.8085, 169.45) -> (-415.956, 169.45)
  line L16 (-264.4867, 126.45) -> (-281.2321, 161.9647)
  line L17 (-264.4867, 126.45) -> (-264.4867, 165.7145)
  line L18 (-263.8509, 141.85) -> (-270.1342, 165.3063)
  line L19 (-268.93, 125.2594) -> (-272.0357, 136.85)
  arc A1 centre (-264.4867, 126.45) radius 4.6 clockwise from (-260.0435, 127.6406) to (-268.93, 125.2594)
  arc A2 centre (-229.7424, 131.35) radius 83.7264 clockwise from (-311.5111, 113.35) to (-313.4688, 131.35)
  circle C1 centre (-264.4867, 126.45) radius 1.6
  arc A3 centre (-274.4187, 51.1532) radius 72.4175 clockwise from (-311.5111, 113.35) to (-278.9967, 123.4258)
  arc A4 centre (-264.4867, 126.45) radius 39.2645 clockwise from (-281.2321, 161.9647) to (-264.4867, 165.7145)
  arc A5 centre (-264.4867, 126.45) radius 4.6 clockwise from (-260.0435, 127.6406) to (-268.93, 125.2594)
  arc A6 centre (-264.4867, 126.45) radius 39.2645 clockwise from (-281.2321, 161.9647) to (-264.4867, 165.7145)
  point P5 (-272.0357, 136.85)
  point P15 (-272.0357, 136.85)
  point P17 (-268.3217, 141.85)
  point P8 (-264.4867, 126.45)
  point P18 (-264.4867, 126.45)
  point P28 (-264.4867, 126.45)
  point P9 (-263.8509, 141.85)
  point P35 (-263.8509, 141.85)
  point P38 (-281.2321, 161.9647)
  point P37 (-264.4867, 165.7145)
  point P36 (-264.4867, 126.45)
  point P30 (-281.2321, 161.9647)
  point P16 (-279.0207, 162.9256)
  point P34 (-270.1342, 165.3063)
  point P29 (-264.4867, 165.7145)
  coincident P5 P15
  coincident L4 P17
  coincident P8 P18
  coincident P18 P28
  vertical L17
  coincident P9 P35
  parallel L8 L18
  coincident L16 P38
  coincident L17 P37
  coincident P18 P36
  coincident P30 A6
  coincident P16 A4
  coincident P34 A6
  dimension "d526" distance L10 P29 = 3.175
extrude "Extrude2" add sketch "Sketch31" profile of A1 L3 L4 C1 L8 A5 L18 A6 against normal blind 10
sketch "trigger linkage hole" plane through (0, 210.7137, -56.4606) normal (0, -0.9659, 0.2588) x axis (1, 0, 0)
  line L1 (-5, 190.5955) -> (-5, 205.3062)
  line L2 (5, 190.5955) -> (-5, 190.5955)
  line L3 (5, 205.3062) -> (5, 190.5955)
  line L4 (-5, 205.3062) -> (5, 205.3062)
  line L5 (-5, 229.5895) -> (-5, 229.8601)
  line L6 (5, 229.5895) -> (-5, 229.5895)
  line L7 (5, 229.8601) -> (5, 229.5895)
  line L8 (-5, 229.5899) -> (5, 229.5899)
  line L9 (0, 238.4937) -> (0, 229.5895)
  circle C1 centre (0, 225.0895) radius 1.5
  point P11 (0, 229.5895)
  point P6 (0, 225.0895)
  point P13 (0, 226.5895)
  midpoint L6 P11
  perpendicular L4 L9
  coincident P6 L9
  coincident C1 P13
  coincident L9 P13
  dimension "d406" diameter C1 = 3
  dimension "d527" distance L6 P13 = 3
extrude "Extrude3" cut sketch "trigger linkage hole" profile of C1 blind -12.7 from offset 0.254
sketch "Sketch1" plane through (-5, 0, 0) normal (-1, 0, 0) x axis (0, -1, 0)
  line L1 (-278.9967, 136.85) -> (-278.9967, 123.4258)
  line L2 (-272.0357, 136.85) -> (-278.9967, 136.85)
  line L3 (-263.8509, 141.85) -> (-260.0435, 127.6406)
  line L4 (-273.375, 141.85) -> (-279.0207, 162.9256)
  line L5 (-319.7775, 141.85) -> (-273.375, 141.85)
  line L6 (-319.7775, 135.65) -> (-319.7775, 141.85)
  line L7 (-313.4688, 135.65) -> (-319.7775, 135.65)
  line L8 (-313.4688, 131.35) -> (-313.4688, 135.65)
  line L9 (-296.5763, 141.85) -> (-279.0207, 162.9256)
  line L10 (-315.5775, 141.85) -> (-319.7775, 137.65)
  line L11 (-268.93, 125.2594) -> (-272.0357, 136.85)
  line L12 (-270.1342, 165.3063) -> (-263.8509, 141.85)
  arc A1 centre (-264.4867, 126.45) radius 4.6 clockwise from (-260.0435, 127.6406) to (-268.93, 125.2594)
  arc A2 centre (-229.7424, 131.35) radius 83.7264 clockwise from (-311.5111, 113.35) to (-313.4688, 131.35)
  arc A3 centre (-274.4187, 51.1532) radius 72.4175 clockwise from (-311.5111, 113.35) to (-278.9967, 123.4258)
  arc A4 centre (-264.4867, 126.45) radius 39.2645 clockwise from (-279.0207, 162.9256) to (-270.1342, 165.3063)
  point P10 (-279.0207, 162.9256)
  point P17 (-279.0207, 162.9256)
  point P18 (-296.5763, 141.85)
  point P19 (-319.7775, 137.65)
  point P20 (-315.5775, 141.85)
  point P13 (-319.7775, 135.65)
  coincident P10 P17
  midpoint L5 P18
  coincident L6 P19
  coincident L5 P20
  dimension "d415" angle L5 L10 = 135
  dimension "d416" distance P13 P19 = 2
extrude "Extrude4" add sketch "Sketch1" profile of L4 L5 L9 against normal blind 2
mirror "Mirror1" mirrorStitchTolerance 0.1
extrude "Extrude5" cut sketch "Sketch1" profile of L5 L6 L10 against normal blind 10
work_plane "WorkPlane1"
sketch "Sketch2" plane through (0, 59.3415, 191.4941) normal (0, 0.296, 0.9552) x axis (-1, 0, 0)
  line L1 (5, -229.9602) -> (-5, -229.9602)
  line L2 (5, -263.9999) -> (5, -229.9602)
  line L3 (-5, -263.9999) -> (5, -263.9999)
  line L4 (-5, -229.9602) -> (-5, -263.9999)
  line L5 (-5, -263.9999) -> (5, -229.9602)
  line L6 (5, -246.9801) -> (0, -246.9801)
  line L7 (5, -231.4801) -> (5, -262.4801)
  line L8 (3.7, -262.4801) -> (3.7, -231.4801)
  line L9 (4.35, -231.4801) -> (4.35, -262.4801)
  line L10 (2.25, -262.4801) -> (2.25, -231.4801)
  line L11 (2.9, -231.4801) -> (2.9, -262.4801)
  line L12 (3.55, -231.4801) -> (3.55, -262.4801)
  line L13 (0.8, -262.4801) -> (0.8, -231.4801)
  line L14 (1.45, -231.4801) -> (1.45, -262.4801)
  line L15 (2.1, -231.4801) -> (2.1, -262.4801)
  line L16 (-0.65, -262.4801) -> (-0.65, -231.4801)
  line L17 (0, -231.4801) -> (0, -262.4801)
  line L18 (0.65, -231.4801) -> (0.65, -262.4801)
  line L19 (-2.1, -262.4801) -> (-2.1, -231.4801)
  line L20 (-1.45, -231.4801) -> (-1.45, -262.4801)
  line L21 (-0.8, -231.4801) -> (-0.8, -262.4801)
  line L22 (-3.55, -262.4801) -> (-3.55, -231.4801)
  line L23 (-2.9, -231.4801) -> (-2.9, -262.4801)
  line L24 (-2.25, -231.4801) -> (-2.25, -262.4801)
  line L25 (-5, -262.4801) -> (-5, -231.4801)
  line L26 (-4.35, -231.4801) -> (-4.35, -262.4801)
  line L27 (-3.7, -231.4801) -> (-3.7, -262.4801)
  arc A1 centre (4.35, -231.4801) radius 0.65 clockwise from (3.7, -231.4801) to (5, -231.4801)
  arc A2 centre (4.35, -262.4801) radius 0.65 clockwise from (5, -262.4801) to (3.7, -262.4801)
  arc A3 centre (2.9, -231.4801) radius 0.65 clockwise from (2.25, -231.4801) to (3.55, -231.4801)
  arc A4 centre (2.9, -262.4801) radius 0.65 clockwise from (3.55, -262.4801) to (2.25, -262.4801)
  arc A5 centre (1.45, -231.4801) radius 0.65 clockwise from (0.8, -231.4801) to (2.1, -231.4801)
  arc A6 centre (1.45, -262.4801) radius 0.65 clockwise from (2.1, -262.4801) to (0.8, -262.4801)
  arc A7 centre (0, -231.4801) radius 0.65 clockwise from (-0.65, -231.4801) to (0.65, -231.4801)
  arc A8 centre (0, -262.4801) radius 0.65 clockwise from (0.65, -262.4801) to (-0.65, -262.4801)
  arc A9 centre (-1.45, -231.4801) radius 0.65 clockwise from (-2.1, -231.4801) to (-0.8, -231.4801)
  arc A10 centre (-1.45, -262.4801) radius 0.65 clockwise from (-0.8, -262.4801) to (-2.1, -262.4801)
  arc A11 centre (-2.9, -231.4801) radius 0.65 clockwise from (-3.55, -231.4801) to (-2.25, -231.4801)
  arc A12 centre (-2.9, -262.4801) radius 0.65 clockwise from (-2.25, -262.4801) to (-3.55, -262.4801)
  arc A13 centre (-4.35, -231.4801) radius 0.65 clockwise from (-5, -231.4801) to (-3.7, -231.4801)
  arc A14 centre (-4.35, -262.4801) radius 0.65 clockwise from (-3.7, -262.4801) to (-5, -262.4801)
  point P3 (5, -229.9602)
  point P6 (5, -229.9602)
  point P5 (-5, -263.9999)
  point P7 (-5, -263.9999)
  point P8 (0, -246.9801)
  point P9 (5, -246.9801)
  point P16 (4.35, -246.9801)
  point P17 (5, -246.9801)
  point P14 (4.35, -262.4801)
  point P15 (4.35, -231.4801)
  coincident P3 P6
  coincident P5 P7
  midpoint L5 P8
  perpendicular L4 L6
  coincident L2 P9
  tangent L7 A1
  tangent A1 L8
  parallel L7 L8
  tangent L8 A2
  tangent L7 A2
  perpendicular L1 L9
  coincident L6 P16
  midpoint L9 P16
  coincident L7 P17
  dimension "d428" diameter A1 = 1.3
  dimension "d429" distance P14 P15 = 31
  dimension "d432" R-Pattern1-uDistance = -8.7
  dimension "d433" R-Pattern1-vDistance = 0
emboss "Emboss1" sketch "Sketch2" Depth 0.75 Horizontal Distance 0 Vertical Distance 0 Rotation Angle 0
